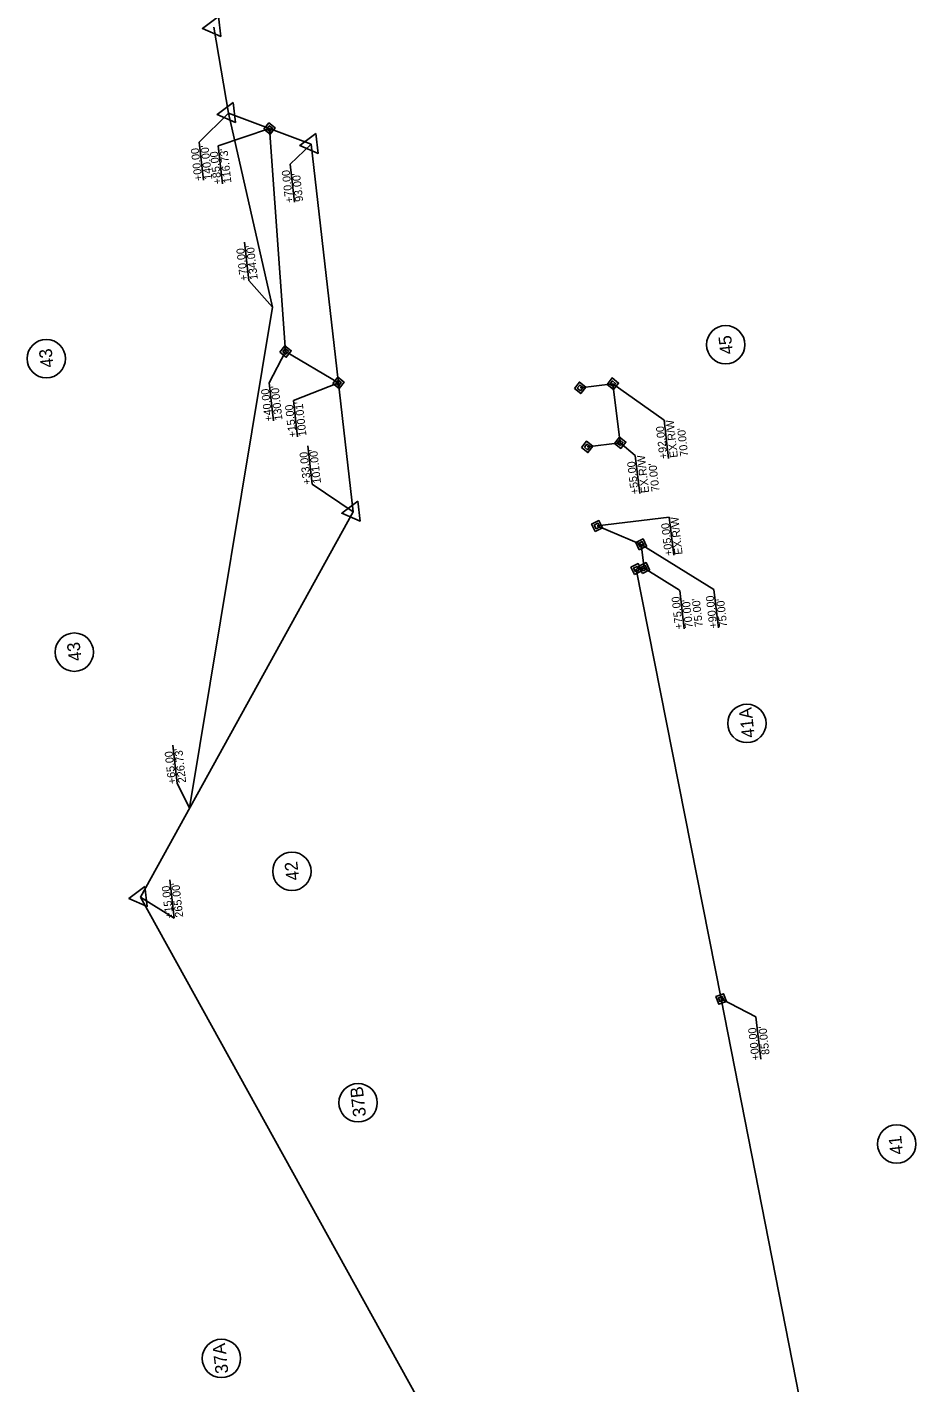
# Model space of a CAD drawing. Extents: x 474184 to 481900, y 489262 to 505659.
# Drawn here: x 478000 to 478556, y 495402 to 496249 of the extents above; entities that cross this region are included whole.
import ezdxf

# ---------------------------------------------------------------- set-up
doc = ezdxf.new("R2010")
doc.units = 0
for name, color, linetype in [('Prop Drainage Structure Drop Inlet Grate 2 Wide Slots and Sag Grates 840 22 CELL', 7, 'Continuous'), ('Prop Drainage Structure Outlet Berm Ditch 850 10 Label', 7, 'Continuous'), ('Prop Drainage Structure Pipe CSP 15in', 7, 'Continuous'), ('Prop Drainage Structure Pipe RCP 18in Class IV', 7, 'Continuous'), ('Prop Drainage Structure Pipe RCP 18in Class IV Label', 7, 'Continuous'), ('Prop Drainage Structure Pipe Side Drain 15in Label', 7, 'Continuous'), ('Prop Drainage Structure Pipe Stub Out CELL', 7, 'Continuous'), ('Prop Drainage Structure Plot Symbol 50 Scale', 7, 'Continuous'), ('Prop Earthen Structure Base Ditch Lateral Detail Label', 7, 'Continuous'), ('Prop Earthen Structure False Sump CELL', 7, 'Continuous'), ('Prop Earthen Structure False Sump Label', 7, 'Continuous')]:
    doc.layers.add(name, color=color, linetype=linetype)

msp = doc.modelspace()

# ---------------------------------------------------------------- linework, layer by layer
at = {"layer": 'Prop Drainage Structure Drop Inlet Grate 2 Wide Slots and Sag Grates 840 22 CELL'}
for p, q in [((478346.21, 496023.62), (478366.62, 496026.23)), ((478371.22, 495989.31), (478366.62, 496026.23)), ((478350.62, 495986.74), (478371.22, 495989.31))]:
    msp.add_line(p, q, dxfattribs=at)
at = {"layer": 'Prop Drainage Structure Outlet Berm Ditch 850 10 Label'}
for p, q in [((478162.05, 496046.38), (478151.99, 496185.67)), ((478195.08, 496026.72), (478162.05, 496046.38)), ((478384.34, 495925.81), (478356.77, 495937.3)), ((478386.27, 495911.01), (478384.34, 495925.81)), ((478381.31, 495910.37), (478386.27, 495911.01)), ((478434.35, 495641.7), (478381.31, 495910.37)), ((478492.88, 495344.14), (478434.35, 495641.7))]:
    msp.add_line(p, q, dxfattribs=at)
at = {"layer": 'Prop Drainage Structure Pipe CSP 15in'}
for p, q in [((478437.23, 496050.58), (478437.23, 496050.58)), ((478012.43, 496041.88), (478012.43, 496041.88)), ((478029.93, 495858.45), (478029.93, 495858.45)), ((478450.45, 495813.92), (478450.45, 495813.92)), ((478165.99, 495721.46), (478165.99, 495721.46)), ((478207.39, 495576.83), (478207.39, 495576.83)), ((478544.13, 495551.06), (478544.13, 495551.06)), ((478121.95, 495417.05), (478121.95, 495417.05)), ((478121.95, 495417.05), (478121.95, 495417.05))]:
    msp.add_line(p, q, dxfattribs=at)
for centre in [(478437.23, 496050.58), (478012.43, 496041.88), (478029.93, 495858.45), (478450.45, 495813.92), (478165.99, 495721.46), (478207.39, 495576.83), (478544.13, 495551.06), (478121.95, 495417.05), (478121.95, 495417.05)]:
    msp.add_circle(centre, 12, dxfattribs=at)
at = {"layer": 'Prop Drainage Structure Pipe RCP 18in Class IV'}
for p, q in [((478117.24, 496249.08), (478117.24, 496249.08)), ((478126.38, 496195.28), (478126.38, 496195.28)), ((478151.99, 496185.67), (478151.99, 496185.67)), ((478178.01, 496175.91), (478178.01, 496175.91)), ((478162.05, 496046.38), (478162.05, 496046.38)), ((478195.08, 496026.72), (478195.08, 496026.72)), ((478366.62, 496026.23), (478366.62, 496026.23)), ((478346.21, 496023.62), (478346.21, 496023.62)), ((478350.62, 495986.74), (478350.62, 495986.74)), ((478371.22, 495989.31), (478371.22, 495989.31)), ((478204.3, 495946.13), (478204.3, 495946.13)), ((478356.77, 495937.3), (478356.77, 495937.3)), ((478384.34, 495925.81), (478384.34, 495925.81)), ((478381.31, 495910.37), (478381.31, 495910.37)), ((478386.27, 495911.01), (478386.27, 495911.01)), ((478071.24, 495705.32), (478071.24, 495705.32)), ((478434.35, 495641.7), (478434.35, 495641.7))]:
    msp.add_line(p, q, dxfattribs=at)
for points in [[(478120.11, 496255.7), (478121.54, 496243.31), (478110.08, 496248.24)], [(478129.25, 496201.9), (478130.68, 496189.5), (478119.22, 496194.43)], [(478180.87, 496182.53), (478182.31, 496170.14), (478170.85, 496175.07)], [(478207.16, 495952.75), (478208.6, 495940.36), (478197.13, 495945.29)], [(478074.1, 495711.94), (478075.54, 495699.55), (478064.08, 495704.48)]]:
    msp.add_lwpolyline(points, close=True, dxfattribs=at)
at = {"layer": 'Prop Drainage Structure Pipe RCP 18in Class IV Label'}
for points in [[(478148.41, 496185.26), (478151.57, 496189.25), (478155.56, 496186.09), (478152.4, 496182.1)], [(478150.2, 496185.47), (478151.78, 496187.46), (478153.77, 496185.88), (478152.19, 496183.89)], [(478158.47, 496045.97), (478161.63, 496049.96), (478165.62, 496046.79), (478162.46, 496042.8)], [(478160.26, 496046.17), (478161.84, 496048.17), (478163.83, 496046.59), (478162.25, 496044.59)], [(478191.5, 496026.31), (478194.67, 496030.3), (478198.65, 496027.14), (478195.49, 496023.15)], [(478193.29, 496026.52), (478194.87, 496028.51), (478196.87, 496026.93), (478195.28, 496024.94)], [(478342.63, 496023.21), (478345.8, 496027.2), (478349.79, 496024.03), (478346.62, 496020.04)], [(478344.42, 496023.41), (478346, 496025.41), (478348, 496023.83), (478346.42, 496021.83)], [(478363.04, 496025.81), (478366.21, 496029.8), (478370.19, 496026.64), (478367.03, 496022.65)], [(478364.83, 496026.02), (478366.41, 496028.02), (478368.41, 496026.43), (478366.82, 496024.44)], [(478347.04, 495986.33), (478350.2, 495990.32), (478354.19, 495987.15), (478351.03, 495983.17)], [(478367.64, 495988.9), (478370.8, 495992.89), (478374.79, 495989.73), (478371.63, 495985.74)], [(478369.43, 495989.11), (478371.01, 495991.1), (478373, 495989.52), (478371.42, 495987.53)], [(478348.83, 495986.54), (478350.41, 495988.53), (478352.4, 495986.95), (478350.82, 495984.95)], [(478355.6, 495933.9), (478353.37, 495938.48), (478357.94, 495940.71), (478360.18, 495936.13)], [(478356.19, 495935.6), (478355.07, 495937.89), (478357.36, 495939), (478358.47, 495936.72)], [(478383.17, 495922.4), (478380.94, 495926.98), (478385.51, 495929.21), (478387.74, 495924.64)], [(478383.75, 495924.11), (478382.64, 495926.39), (478384.93, 495927.51), (478386.04, 495925.22)], [(478385.1, 495907.61), (478382.86, 495912.19), (478387.44, 495914.42), (478389.67, 495909.84)], [(478380.14, 495906.96), (478377.91, 495911.54), (478382.48, 495913.77), (478384.71, 495909.19)], [(478380.72, 495908.66), (478379.61, 495910.95), (478381.9, 495912.07), (478383.01, 495909.78)], [(478385.68, 495909.31), (478384.57, 495911.6), (478386.85, 495912.72), (478387.97, 495910.43)], [(478437.62, 495640.2), (478432.86, 495638.42), (478431.08, 495643.19), (478435.84, 495644.97)], [(478435.99, 495640.95), (478433.6, 495640.06), (478432.71, 495642.45), (478435.1, 495643.34)]]:
    msp.add_lwpolyline(points, close=True, dxfattribs=at)
at = {"layer": 'Prop Drainage Structure Pipe Side Drain 15in Label'}
for p, q in [((478126.38, 496195.28), (478117.24, 496249.08)), ((478178.01, 496175.91), (478126.38, 496195.28)), ((478204.3, 495946.13), (478178.01, 496175.91)), ((478071.24, 495705.32), (478204.3, 495946.13)), ((478288.06, 495313.78), (478071.24, 495705.32))]:
    msp.add_line(p, q, dxfattribs=at)
at = {"layer": 'Prop Drainage Structure Pipe Stub Out CELL'}
for p, q in [((478153.86, 496074.16), (478126.38, 496195.28)), ((478102.04, 495761.06), (478153.86, 496074.16))]:
    msp.add_line(p, q, dxfattribs=at)
at = {"layer": 'Prop Drainage Structure Plot Symbol 50 Scale'}
for p, q in [((478108, 496177.23), (478110.76, 496153.34)), ((478164.84, 496163.48), (478167.59, 496139.59)), ((478175.88, 495987.37), (478178.64, 495963.48)), ((478089.73, 495716.19), (478092.48, 495692.3)), ((478092.48, 495692.3), (478071.24, 495705.32))]:
    msp.add_line(p, q, dxfattribs=at)
for points in [[(478108, 496177.23), (478126.19, 496195.09)], [(478164.84, 496163.48), (478178.01, 496175.91)], [(478178.64, 495963.48), (478204.3, 495946.13)]]:
    msp.add_lwpolyline(points, dxfattribs=at)
at = {"layer": 'Prop Earthen Structure Base Ditch Lateral Detail Label'}
for p, q in [((478119.85, 496174.97), (478122.59, 496151.24)), ((478151.8, 496026.82), (478154.56, 496002.93)), ((478166.94, 496015.69), (478169.56, 495992.99)), ((478401.95, 495942.88), (478404.71, 495918.99)), ((478408.46, 495896.95), (478411.21, 495873.06)), ((478429.88, 495897.56), (478432.64, 495873.67)), ((478434.35, 495641.7), (478456.12, 495630.54)), ((478456.12, 495630.54), (478459.16, 495604.14))]:
    msp.add_line(p, q, dxfattribs=at)
for points in [[(478119.85, 496174.97), (478151.99, 496185.67)], [(478151.8, 496026.82), (478162.05, 496046.38)], [(478166.94, 496015.69), (478195.08, 496026.72)], [(478401.95, 495942.88), (478356.77, 495937.3)], [(478429.88, 495897.56), (478384.34, 495925.81)], [(478408.26, 495897.11), (478386.27, 495911.01)]]:
    msp.add_lwpolyline(points, dxfattribs=at)
at = {"layer": 'Prop Earthen Structure False Sump CELL'}
for p, q in [((478398.68, 496003.43), (478401.44, 495979.54)), ((478380.71, 495981.4), (478383.47, 495957.52))]:
    msp.add_line(p, q, dxfattribs=at)
for points in [[(478398.68, 496003.43), (478366.62, 496026.23)], [(478380.71, 495981.4), (478371.22, 495989.31)]]:
    msp.add_lwpolyline(points, dxfattribs=at)
at = {"layer": 'Prop Earthen Structure False Sump Label'}
for p, q in [((478136.26, 496114.65), (478139.02, 496090.76)), ((478091.44, 495800.23), (478094.19, 495776.35))]:
    msp.add_line(p, q, dxfattribs=at)
for points in [[(478139.02, 496090.76), (478153.86, 496074.16)], [(478094.19, 495776.35), (478102.04, 495761.06)]]:
    msp.add_lwpolyline(points, dxfattribs=at)

# ---------------------------------------------------------------- texts
at = {"layer": 'Prop Drainage Structure Pipe CSP 15in'}
for s, p in [('45', (478441.9, 496044.98)), ('43', (478017.05, 496036.73)), ('43', (478034.55, 495853.3)), ('41A', (478455.47, 495805.34)), ('42', (478170.63, 495716.18)), ('37B', (478212.38, 495568.51)), ('41', (478548.21, 495544.85)), ('37A', (478126.34, 495407.99))]:
    msp.add_text(s, height=8, rotation=96.57729, dxfattribs=at).set_placement(p)
at = {"layer": 'Prop Drainage Structure Plot Symbol 50 Scale'}
for s, p in [('+00.00', (478110.04, 496153.26)), ("140.00'", (478116.25, 496153.98)), ('+70.00', (478166.87, 496139.51)), ("93.00'", (478173.08, 496140.22)), ('+33.00', (478178.02, 495963.41)), ("101.00'", (478184.22, 495964.12)), ('+15.00', (478091.86, 495692.23)), ("265.00'", (478098.07, 495692.94))]:
    msp.add_text(s, height=5, rotation=96.57729, dxfattribs=at).set_placement(p)
at = {"layer": 'Prop Earthen Structure Base Ditch Lateral Detail Label'}
for s, rotation, p in [('+85.00', 96.57729, (478121.97, 496151.16)), ("116.73'", 96.57729, (478128.18, 496151.88)), ("130.00'", 96.57729, (478160.15, 496003.58)), ('+40.00', 96.57729, (478153.94, 496002.86)), ('+15.00', 96.57729, (478168.94, 495992.92)), ("100.01'", 96.57729, (478175.15, 495993.64)), ('EX.R/W', 96.57729, (478410.29, 495919.63)), ('+05.00', 96.57729, (478404.09, 495918.92)), ('+75.00', 96.57729, (478410.59, 495872.99)), ("70.00'", 96.57729, (478416.8, 495873.71)), ("75.00'", 96.57729, (478423.01, 495874.42)), ('+90.00', 96.57729, (478432.02, 495873.6)), ("75.00'", 96.57729, (478438.23, 495874.31)), ('+00.00', 96.56297, (478458.46, 495603.57)), ("85.00'", 96.56297, (478464.66, 495607.06))]:
    msp.add_text(s, height=5, rotation=rotation, dxfattribs=at).set_placement(p)
at = {"layer": 'Prop Earthen Structure False Sump CELL'}
for s, p in [('+92.00', (478400.83, 495979.48)), ('EX.R/W', (478407.34, 495980.23)), ("70.00'", (478413.85, 495980.98)), ('+55.00', (478382.86, 495957.45)), ('EX.R/W', (478389.37, 495958.2)), ("70.00'", (478395.88, 495958.95))]:
    msp.add_text(s, height=5, rotation=96.57729, dxfattribs=at).set_placement(p)
at = {"layer": 'Prop Earthen Structure False Sump Label'}
for s, p in [('+70.00', (478138.49, 496090.7)), ("134.00'", (478144.7, 496091.41)), ('+65.00', (478093.67, 495776.29)), ("226.73'", (478099.87, 495777))]:
    msp.add_text(s, height=5, rotation=96.57729, dxfattribs=at).set_placement(p)

doc.saveas('drawing.dxf')
